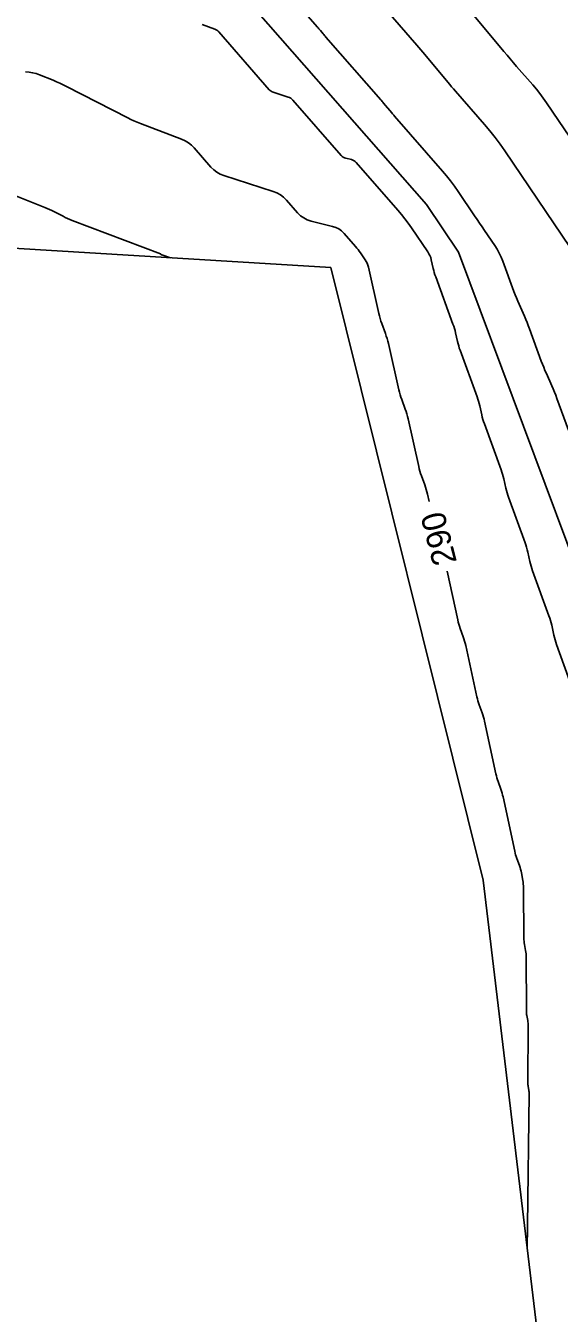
# Model space of a CAD drawing. Extents: x 1574966 to 1597594, y 720505 to 737840.
# Drawn here: x 1577874.4 to 1578007.3, y 723907.8 to 724228.5 of the extents above; entities that cross this region are included whole.
import ezdxf

# ---------------------------------------------------------------- set-up
doc = ezdxf.new("R2010")
doc.units = 0
for name, color, linetype in [('R_Contour Annot', 7, 'Continuous'), ('R_Contours', 7, 'Continuous'), ('S_BREAKLINE', 7, 'Continuous')]:
    doc.layers.add(name, color=color, linetype=linetype)

msp = doc.modelspace()

# ---------------------------------------------------------------- linework, layer by layer
at = {"layer": 'R_Contours'}
for points in [[(1577933.47, 724243.8), (1577947.09, 724228.22), (1577947.27, 724228.01), (1577947.45, 724227.81), (1577947.62, 724227.6), (1577947.8, 724227.39), (1577948.49, 724226.56), (1577948.67, 724226.35), (1577948.84, 724226.14), (1577949.02, 724225.93), (1577949.19, 724225.73), (1577962.85, 724210.1), (1577963.03, 724209.9), (1577963.21, 724209.69), (1577963.38, 724209.49), (1577963.55, 724209.28), (1577965.59, 724206.83), (1577965.76, 724206.63), (1577965.93, 724206.43), (1577966.1, 724206.23), (1577966.27, 724206.03), (1577978.24, 724192.33), (1577979.27, 724191.12), (1577980.26, 724189.87), (1577981.21, 724188.6), (1577982.12, 724187.29), (1577986.22, 724181.23), (1577986.85, 724180.3), (1577987.48, 724179.38), (1577988.1, 724178.45), (1577988.73, 724177.52), (1577991.26, 724173.82), (1577991.85, 724172.88), (1577992.39, 724171.91), (1577992.87, 724170.9), (1577993.29, 724169.86), (1577996.05, 724162.3), (1577996.35, 724161.52), (1577996.65, 724160.74), (1577996.97, 724159.97), (1577997.31, 724159.2), (1577998.66, 724156.15), (1577999, 724155.38), (1577999.32, 724154.61), (1577999.62, 724153.84), (1577999.92, 724153.05), (1578002.85, 724145.02), (1578003.15, 724144.23), (1578003.46, 724143.45), (1578003.78, 724142.67), (1578004.12, 724141.9), (1578005.49, 724138.83), (1578005.83, 724138.05), (1578006.15, 724137.28), (1578006.46, 724136.49), (1578006.75, 724135.71), (1578009.66, 724127.76)], [(1577963.02, 724233.81), (1577971.85, 724223.7), (1577972.35, 724223.13), (1577972.84, 724222.56), (1577973.33, 724221.98), (1577973.82, 724221.4), (1577979.56, 724214.48), (1577980.04, 724213.91), (1577980.52, 724213.35), (1577981, 724212.79), (1577981.49, 724212.23), (1577988.72, 724203.95), (1577990.07, 724202.36), (1577991.36, 724200.74), (1577992.6, 724199.07), (1577993.79, 724197.37), (1578010.08, 724173.27)], [(1577984.08, 724233.52), (1577993.54, 724222.14), (1577994.32, 724221.2), (1577995.11, 724220.27), (1577995.9, 724219.34), (1577996.7, 724218.42), (1578000.71, 724213.84), (1578001.63, 724212.75), (1578002.51, 724211.64), (1578003.36, 724210.51), (1578004.17, 724209.34), (1578014.5, 724194.07)], [(1577918.36, 724228.9), (1577921.53, 724227.69), (1577921.8, 724227.57), (1577922.04, 724227.42), (1577922.27, 724227.24), (1577922.48, 724227.03), (1577935.06, 724212.62), (1577935.27, 724212.4), (1577935.51, 724212.22), (1577935.76, 724212.08), (1577936.05, 724211.97), (1577939.8, 724210.77), (1577940.12, 724210.64), (1577940.41, 724210.48), (1577940.68, 724210.28), (1577940.92, 724210.03), (1577952.95, 724196.26), (1577953.21, 724196.01), (1577953.49, 724195.81), (1577953.8, 724195.65), (1577954.13, 724195.54), (1577955.54, 724195.19), (1577955.88, 724195.08), (1577956.19, 724194.93), (1577956.47, 724194.72), (1577956.72, 724194.47), (1577967.12, 724182.58), (1577968.02, 724181.52), (1577968.88, 724180.44), (1577969.71, 724179.33), (1577970.51, 724178.2), (1577974.57, 724172.22), (1577974.86, 724171.76), (1577975.1, 724171.27), (1577975.29, 724170.77), (1577975.44, 724170.24), (1577975.92, 724168.09), (1577976.05, 724167.56), (1577976.2, 724167.03), (1577976.36, 724166.5), (1577976.54, 724165.99), (1577980.85, 724154.22), (1577981.04, 724153.69), (1577981.21, 724153.15), (1577981.36, 724152.61), (1577981.49, 724152.06), (1577981.98, 724149.86), (1577982.12, 724149.31), (1577982.27, 724148.76), (1577982.43, 724148.23), (1577982.62, 724147.69), (1577986.87, 724136.08), (1577987.06, 724135.53), (1577987.23, 724134.98), (1577987.38, 724134.42), (1577987.52, 724133.86), (1577988.02, 724131.6), (1577988.16, 724131.04), (1577988.31, 724130.48), (1577988.48, 724129.93), (1577988.67, 724129.39), (1577992.86, 724117.92), (1577993.05, 724117.36), (1577993.23, 724116.79), (1577993.38, 724116.22), (1577993.52, 724115.65), (1577994.03, 724113.33), (1577994.17, 724112.76), (1577994.33, 724112.19), (1577994.5, 724111.62), (1577994.69, 724111.06), (1577998.82, 724099.75), (1577999.02, 724099.18), (1577999.2, 724098.6), (1577999.36, 724098.01), (1577999.5, 724097.42), (1578000.02, 724095.05), (1578000.16, 724094.45), (1578000.32, 724093.87), (1578000.5, 724093.29), (1578000.69, 724092.72), (1578004.75, 724081.56), (1578004.96, 724080.98), (1578005.14, 724080.38), (1578005.3, 724079.78), (1578005.45, 724079.18), (1578005.98, 724076.74), (1578006.12, 724076.14), (1578006.28, 724075.54), (1578006.46, 724074.94), (1578006.67, 724074.35), (1578010.66, 724063.36)], [(1577974.89, 724110.05), (1577974.5, 724111.81), (1577974.36, 724112.4), (1577974.2, 724112.98), (1577974.02, 724113.57), (1577973.82, 724114.14), (1577972.98, 724116.43), (1577972.78, 724117.01), (1577972.6, 724117.59), (1577972.44, 724118.18), (1577972.3, 724118.77), (1577969.66, 724130.59), (1577969.51, 724131.2), (1577969.34, 724131.82), (1577969.15, 724132.42), (1577968.95, 724133.02), (1577968.07, 724135.41), (1577967.86, 724136.01), (1577967.68, 724136.61), (1577967.51, 724137.22), (1577967.36, 724137.84), (1577964.77, 724149.34), (1577964.62, 724149.98), (1577964.44, 724150.62), (1577964.24, 724151.25), (1577964.03, 724151.87), (1577963.12, 724154.35), (1577962.9, 724154.97), (1577962.71, 724155.6), (1577962.53, 724156.24), (1577962.37, 724156.88), (1577959.76, 724168.41), (1577959.63, 724168.9), (1577959.45, 724169.37), (1577959.22, 724169.82), (1577958.96, 724170.26), (1577957.81, 724171.95), (1577957.51, 724172.36), (1577957.21, 724172.77), (1577956.89, 724173.17), (1577956.56, 724173.56), (1577953.72, 724176.81), (1577953.1, 724177.42), (1577952.41, 724177.92), (1577951.65, 724178.3), (1577950.83, 724178.57), (1577945.51, 724179.88), (1577944.54, 724180.2), (1577943.65, 724180.65), (1577942.84, 724181.23), (1577942.11, 724181.95), (1577939.38, 724185.09), (1577938.65, 724185.81), (1577937.85, 724186.42), (1577936.98, 724186.91), (1577936.02, 724187.29), (1577923.73, 724191.2), (1577922.82, 724191.56), (1577921.98, 724192.03), (1577921.22, 724192.61), (1577920.53, 724193.3), (1577916.33, 724198.11), (1577915.66, 724198.8), (1577914.92, 724199.38), (1577914.12, 724199.87), (1577913.24, 724200.26), (1577902.95, 724204.18), (1577902.15, 724204.5), (1577901.35, 724204.84), (1577900.57, 724205.2), (1577899.79, 724205.59), (1577884.53, 724213.44), (1577883.71, 724213.85), (1577882.88, 724214.24), (1577882.05, 724214.61), (1577881.21, 724214.96), (1577877.81, 724216.31), (1577876.96, 724216.62), (1577876.08, 724216.84), (1577875.2, 724217), (1577874.29, 724217.08)], [(1577869.59, 724187.1), (1577879.12, 724183.29), (1577879.7, 724183.05), (1577880.28, 724182.79), (1577880.86, 724182.52), (1577881.42, 724182.24), (1577883.68, 724181.08), (1577884.25, 724180.8), (1577884.82, 724180.53), (1577885.4, 724180.28), (1577885.99, 724180.05), (1577907.96, 724171.7), (1577907.99, 724171.68), (1577908.02, 724171.66), (1577908.05, 724171.64), (1577908.07, 724171.62), (1577908.16, 724171.51), (1577908.19, 724171.49), (1577908.21, 724171.47), (1577908.24, 724171.45), (1577908.28, 724171.44), (1577910.5, 724170.73)], [(1577999.33, 723924.12), (1577999.44, 723929.22), (1577999.44, 723929.25), (1577999.44, 723929.28), (1577999.44, 723929.31), (1577999.43, 723929.34), (1577999.41, 723929.47), (1577999.41, 723929.5), (1577999.4, 723929.53), (1577999.4, 723929.56), (1577999.4, 723929.59), (1577999.83, 723962.47), (1577999.82, 723962.69), (1577999.81, 723962.92), (1577999.79, 723963.14), (1577999.75, 723963.37), (1577999.59, 723964.26), (1577999.56, 723964.48), (1577999.54, 723964.71), (1577999.52, 723964.93), (1577999.52, 723965.16), (1577999.58, 723979.44), (1577999.58, 723979.75), (1577999.56, 723980.06), (1577999.52, 723980.37), (1577999.47, 723980.68), (1577999.25, 723981.92), (1577999.21, 723982.23), (1577999.17, 723982.54), (1577999.15, 723982.85), (1577999.14, 723983.17), (1577999.1, 723996.54), (1577999.09, 723996.93), (1577999.06, 723997.33), (1577999.02, 723997.72), (1577998.96, 723998.11), (1577998.68, 723999.66), (1577998.62, 724000.05), (1577998.57, 724000.44), (1577998.54, 724000.83), (1577998.53, 724001.23), (1577998.4, 724013.76), (1577998.39, 724014.23), (1577998.35, 724014.69), (1577998.3, 724015.16), (1577998.22, 724015.62), (1577997.89, 724017.48), (1577997.8, 724017.94), (1577997.69, 724018.39), (1577997.56, 724018.84), (1577997.4, 724019.29), (1577996.76, 724021.08), (1577996.6, 724021.53), (1577996.46, 724021.98), (1577996.34, 724022.44), (1577996.23, 724022.9), (1577993.35, 724036.4), (1577993.23, 724036.89), (1577993.1, 724037.37), (1577992.96, 724037.85), (1577992.79, 724038.33), (1577992.11, 724040.22), (1577991.94, 724040.69), (1577991.8, 724041.17), (1577991.67, 724041.66), (1577991.55, 724042.14), (1577988.71, 724055.29), (1577988.59, 724055.81), (1577988.45, 724056.32), (1577988.3, 724056.83), (1577988.13, 724057.33), (1577987.4, 724059.32), (1577987.23, 724059.82), (1577987.07, 724060.33), (1577986.94, 724060.84), (1577986.81, 724061.35), (1577984.03, 724074.16), (1577983.9, 724074.7), (1577983.75, 724075.24), (1577983.59, 724075.77), (1577983.41, 724076.3), (1577982.65, 724078.39), (1577982.46, 724078.92), (1577982.3, 724079.45), (1577982.15, 724079.98), (1577982.03, 724080.53), (1577979.37, 724092.62)]]:
    msp.add_lwpolyline(points, dxfattribs=at)
at = {"layer": 'S_BREAKLINE'}
for p, q in [((1577908.87, 724258.56), (1577974.26, 724183.98)), ((1577974.26, 724183.98), (1577982.26, 724172.17)), ((1577836.88, 724175.22), (1577950.4, 724168.3)), ((1577982.26, 724172.17), (1578035.49, 724029.31)), ((1577950.4, 724168.3), (1577988.37, 724015.7)), ((1577988.37, 724015.7), (1578004.94, 723877.29))]:
    msp.add_line(p, q, dxfattribs=at)

# ---------------------------------------------------------------- texts
at = {"layer": 'R_Contour Annot'}
msp.add_text('290', height=6, rotation=104.4281, dxfattribs=at).set_placement((1577981.86, 724094.97))

doc.saveas('drawing.dxf')
